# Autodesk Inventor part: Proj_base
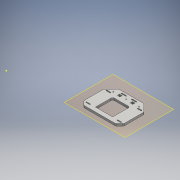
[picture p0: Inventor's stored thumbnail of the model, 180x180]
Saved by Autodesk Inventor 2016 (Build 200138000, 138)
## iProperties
Created: 2015-11
Part Number: Proj_base
Material: Generic
Document SubType Name: Modeling
Designer: John
Density: 1 g/cm^3
Appearance: Default
Author: John
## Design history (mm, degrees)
workplane "Work Plane1"
sketch "Sketch1"
  geometry: L1 (78.45, 44.2)-(78.45, -44.2) reference; L2 (63.45, -59.2)-(-63.45, -59.2) reference; L3 (-78.45, -44.2)-(-78.45, 44.2) reference; L4 (-63.45, 59.2)-(63.45, 59.2) reference; L5 (-161.15, -69.113)-(-161.15, -114.2) reference; L6 (-146.15, -129.2)-(-94.113, -129.2) reference; L7 (-83.507, -124.807)-(-66.893, -108.193) reference; L8 (-56.287, -103.8)-(56.287, -103.8) reference; L9 (66.893, -108.193)-(83.507, -124.807) reference; L10 (94.113, -129.2)-(146.15, -129.2) reference; L11 (161.15, -114.2)-(161.15, -69.113) reference; L12 (156.757, -58.507)-(140.143, -41.893) reference; L13 (135.75, -31.287)-(135.75, 31.287) reference; L14 (140.143, 41.893)-(156.757, 58.507) reference; L15 (161.15, 69.113)-(161.15, 114.2) reference; L16 (146.15, 129.2)-(94.113, 129.2) reference; L17 (83.507, 124.807)-(66.893, 108.193) reference; L18 (56.287, 103.8)-(-56.287, 103.8) reference; L19 (-66.893, 108.193)-(-83.507, 124.807) reference; L20 (-94.113, 129.2)-(-146.15, 129.2) reference; L21 (-161.15, 114.2)-(-161.15, 69.113) reference; L22 (-156.757, 58.507)-(-140.143, 41.893) reference; L23 (-135.75, 31.287)-(-135.75, -31.287) reference; L24 (-140.143, -41.893)-(-156.757, -58.507) reference; L25 (-93.775, 49.2)-(-93.775, 69.2) reference; L26 (-88.525, 69.2)-(-88.525, 49.2) reference; L27 (88.525, -69.2)-(88.525, -49.2) reference; L28 (93.775, -49.2)-(93.775, -69.2) reference; L29 (88.525, 49.2)-(88.525, 69.2) reference; L30 (93.775, 69.2)-(93.775, 49.2) reference; L31 (-93.775, -69.2)-(-93.775, -49.2) reference; L32 (-88.525, -49.2)-(-88.525, -69.2) reference; L33 (-116.55, 81.9)-(116.55, 81.9); L34 (116.55, 81.9)-(116.55, -81.9); L35 (116.55, -81.9)-(-116.55, -81.9); L36 (-116.55, -81.9)-(-116.55, 81.9); C1 r 19.5 at (-128.95, -97) reference; C2 r 19.5 at (-128.95, 97) reference; C3 r 19.5 at (128.95, 97) reference; C4 r 19.5 at (128.95, -97) reference; A1 r 15 centre (63.45, -44.2) between (63.45, -59.2) and (78.45, -44.2) reference; A2 r 15 centre (-63.45, -44.2) between (-78.45, -44.2) and (-63.45, -59.2) reference; A3 r 15 centre (-63.45, 44.2) between (-63.45, 59.2) and (-78.45, 44.2) reference; A4 r 15 centre (63.45, 44.2) between (78.45, 44.2) and (63.45, 59.2) reference; A5 r 15 centre (-146.15, -69.113) between (-156.757, -58.507) and (-161.15, -69.113) reference; A6 r 15 centre (-146.15, -114.2) between (-161.15, -114.2) and (-146.15, -129.2) reference; A7 r 15 centre (-94.113, -114.2) between (-94.113, -129.2) and (-83.507, -124.807) reference; A8 r 15 centre (-56.287, -118.8) between (-56.287, -103.8) and (-66.893, -108.193) reference; A9 r 15 centre (56.287, -118.8) between (66.893, -108.193) and (56.287, -103.8) reference; A10 r 15 centre (94.113, -114.2) between (83.507, -124.807) and (94.113, -129.2) reference; A11 r 15 centre (146.15, -114.2) between (146.15, -129.2) and (161.15, -114.2) reference; A12 r 15 centre (146.15, -69.113) between (161.15, -69.113) and (156.757, -58.507) reference; A13 r 15 centre (150.75, -31.287) between (135.75, -31.287) and (140.143, -41.893) reference; A14 r 15 centre (150.75, 31.287) between (140.143, 41.893) and (135.75, 31.287) reference; A15 r 15 centre (146.15, 69.113) between (156.757, 58.507) and (161.15, 69.113) reference; A16 r 15 centre (146.15, 114.2) between (161.15, 114.2) and (146.15, 129.2) reference; A17 r 15 centre (94.113, 114.2) between (94.113, 129.2) and (83.507, 124.807) reference; A18 r 15 centre (56.287, 118.8) between (56.287, 103.8) and (66.893, 108.193) reference; A19 r 15 centre (-56.287, 118.8) between (-66.893, 108.193) and (-56.287, 103.8) reference; A20 r 15 centre (-94.113, 114.2) between (-83.507, 124.807) and (-94.113, 129.2) reference; A21 r 15 centre (-146.15, 114.2) between (-146.15, 129.2) and (-161.15, 114.2) reference; A22 r 15 centre (-146.15, 69.113) between (-161.15, 69.113) and (-156.757, 58.507) reference; A23 r 15 centre (-150.75, 31.287) between (-135.75, 31.287) and (-140.143, 41.893) reference; A24 r 15 centre (-150.75, -31.287) between (-140.143, -41.893) and (-135.75, -31.287) reference; A25 r 2.625 centre (-91.15, 49.2) between (-93.775, 49.2) and (-88.525, 49.2) reference; A26 r 2.625 centre (-91.15, 69.2) between (-88.525, 69.2) and (-93.775, 69.2) reference; A27 r 2.625 centre (91.15, -69.2) between (88.525, -69.2) and (93.775, -69.2) reference; A28 r 2.625 centre (91.15, -49.2) between (93.775, -49.2) and (88.525, -49.2) reference; A29 r 2.625 centre (91.15, 49.2) between (88.525, 49.2) and (93.775, 49.2) reference; A30 r 2.625 centre (91.15, 69.2) between (93.775, 69.2) and (88.525, 69.2) reference; A31 r 2.625 centre (-91.15, -69.2) between (-93.775, -69.2) and (-88.525, -69.2) reference; A32 r 2.625 centre (-91.15, -49.2) between (-88.525, -49.2) and (-93.775, -49.2) reference; 1 further point
  constraints: 8 end point, 2 parallel, 1 horizontal, 1 perpendicular
  dimensions: "d0" = 12.7 distance from line of A26.centre L33; "d1" = 25.4 distance from line of A26.centre L36; "d2" = 25.4 distance from line of A30.centre L34 (= d1); "d3" = 12.7 distance from line of A27.centre L35 (= d0)
extrude "Extrusion1" new body sketch "Sketch1" distance "d4" = 12.7; taper "d5" = 0 deg
sketch "Sketch2"
  geometry: L1 (93.775, 69.2)-(93.775, 49.2) reference; L2 (88.525, 49.2)-(88.525, 69.2) reference; L3 (93.775, -49.2)-(93.775, -69.2) reference; L4 (88.525, -69.2)-(88.525, -49.2) reference; L5 (-88.525, -49.2)-(-88.525, -69.2) reference; L6 (-93.775, -69.2)-(-93.775, -49.2) reference; L7 (-88.525, 69.2)-(-88.525, 49.2) reference; L8 (-93.775, 49.2)-(-93.775, 69.2) reference; L9 (-101.15, 59.2)-(-81.15, 59.2); L10 (-101.15, 61.825)-(-81.15, 61.825); L11 (-81.15, 56.575)-(-101.15, 56.575); L12 (-101.15, -59.2)-(-81.15, -59.2); L13 (-101.15, -56.575)-(-81.15, -56.575); L14 (-81.15, -61.825)-(-101.15, -61.825); L15 (81.15, -59.2)-(101.15, -59.2); L16 (81.15, -56.575)-(101.15, -56.575); L17 (101.15, -61.825)-(81.15, -61.825); L18 (81.15, 59.2)-(101.15, 59.2); L19 (81.15, 56.575)-(101.15, 56.575); L20 (101.15, 61.825)-(81.15, 61.825); A1 r 2.625 centre (91.15, 69.2) between (93.775, 69.2) and (88.525, 69.2) reference; A2 r 2.625 centre (91.15, 49.2) between (88.525, 49.2) and (93.775, 49.2) reference; A3 r 2.625 centre (91.15, -69.2) between (88.525, -69.2) and (93.775, -69.2) reference; A4 r 2.625 centre (91.15, -49.2) between (93.775, -49.2) and (88.525, -49.2) reference; A5 r 2.625 centre (-91.15, -69.2) between (-93.775, -69.2) and (-88.525, -69.2) reference; A6 r 2.625 centre (-91.15, -49.2) between (-88.525, -49.2) and (-93.775, -49.2) reference; A7 r 2.625 centre (-91.15, 49.2) between (-93.775, 49.2) and (-88.525, 49.2) reference; A8 r 2.625 centre (-91.15, 69.2) between (-88.525, 69.2) and (-93.775, 69.2) reference; A9 r 2.625 centre (-101.15, 59.2) between (-101.15, 61.825) and (-101.15, 56.575); A10 r 2.625 centre (-81.15, 59.2) between (-81.15, 56.575) and (-81.15, 61.825); A11 r 2.625 centre (-101.15, -59.2) between (-101.15, -56.575) and (-101.15, -61.825); A12 r 2.625 centre (-81.15, -59.2) between (-81.15, -61.825) and (-81.15, -56.575); A13 r 2.625 centre (81.15, -59.2) between (81.15, -56.575) and (81.15, -61.825); A14 r 2.625 centre (101.15, -59.2) between (101.15, -61.825) and (101.15, -56.575); A15 r 2.625 centre (81.15, 59.2) between (81.15, 61.825) and (81.15, 56.575); A16 r 2.625 centre (101.15, 59.2) between (101.15, 56.575) and (101.15, 61.825); 5 further points
  constraints: 32 end point, 16 point on circle, 16 tangent, 8 centre point, 5 parallel, 4 equal length, 4 midpoint, 4 vertical alignment, 3 equal radius, 2 horizontal, 2 horizontal alignment, 2 point on line
  dimensions: "d7" = 5.25 distance between parallel lines of L10 L11; "d8" = 10 distance of A6.centre point (-91.15, -59.2); "d9" = 10 distance of A8.centre point (-91.15, 59.2) (= d8)
extrude "Extrusion2" cut sketch "Sketch2" stored distance "d10" = 12.7; taper "d11" = 0 deg
sketch "Sketch3"
  geometry: 1 further point
sketch "Sketch4"
  geometry: L1 (-101.15, 61.825)-(-81.15, 61.825) reference; L2 (-81.15, 56.575)-(-101.15, 56.575) reference; L3 (81.15, -56.575)-(101.15, -56.575) reference; L4 (101.15, -61.825)-(81.15, -61.825) reference; L5 (101.15, 56.575)-(81.15, 56.575) reference; L6 (81.15, 61.825)-(101.15, 61.825) reference; L7 (-101.15, -56.575)-(-81.15, -56.575) reference; L8 (-81.15, -61.825)-(-101.15, -61.825) reference; L9 (116.55, 81.9)-(-116.55, 81.9) reference; L10 (-116.55, 81.9)-(-116.55, -81.9) reference; L11 (-116.55, -81.9)-(116.55, -81.9) reference; L12 (116.55, -81.9)-(116.55, 81.9) reference; L13 (-45, 48.4)-(-30, 48.4); L14 (-30, 48.4)-(-30, 35.4); L15 (-30, 35.4)-(-45, 35.4); L16 (-45, 35.4)-(-45, 48.4); L17 (30, 48.4)-(45, 48.4); L18 (45, 48.4)-(45, 35.4); L19 (45, 35.4)-(30, 35.4); L20 (30, 35.4)-(30, 48.4); C1 r 2.625 at (0, 41.9); C2 r 2.625 at (75, 41.9); C3 r 2.625 at (-75, 41.9); A1 r 2.625 centre (-101.15, 59.2) between (-101.15, 61.825) and (-101.15, 56.575) reference; A2 r 2.625 centre (-81.15, 59.2) between (-81.15, 56.575) and (-81.15, 61.825) reference; A3 r 2.625 centre (81.15, -59.2) between (81.15, -56.575) and (81.15, -61.825) reference; A4 r 2.625 centre (101.15, -59.2) between (101.15, -61.825) and (101.15, -56.575) reference; A5 r 2.625 centre (101.15, 59.2) between (101.15, 56.575) and (101.15, 61.825) reference; A6 r 2.625 centre (81.15, 59.2) between (81.15, 61.825) and (81.15, 56.575) reference; A7 r 2.625 centre (-101.15, -59.2) between (-101.15, -56.575) and (-101.15, -61.825) reference; A8 r 2.625 centre (-81.15, -59.2) between (-81.15, -61.825) and (-81.15, -56.575) reference; 6 further points
  constraints: 16 end point, 5 midpoint, 4 horizontal alignment, 4 parallel, 3 centre point, 2 equal radius, 2 horizontal, 2 perpendicular, 2 point on line, 1 collinear, 1 vertical alignment
  dimensions: "d12" = 30 distance from line of C1.centre L14; "d13" = 5.25 diameter of C1; "d14" = 30 distance from line of L16 C3.centre (= d12); "d15" = 30 distance of point (45, 41.9) C2.centre (= d12); "d16" = 30 distance from line of C1.centre L20 (= d12); "d17" = 13 distance between parallel lines of L15 L13; "d18" = 15 distance of L14.end L15.end; "d19" = 40 distance from line of L9 C1.centre
extrude "Extrusion3" cut sketch "Sketch4" stored distance "d20" = 12.7; taper "d21" = 0 deg
sketch "Sketch5"
  geometry: L1 (-45, 35.4)-(-45, 48.4) reference; L2 (-45, 48.4)-(-30, 48.4) reference; L3 (-30, 48.4)-(-30, 35.4) reference; L4 (-30, 35.4)-(-45, 35.4) reference; L5 (30, 35.4)-(30, 48.4) reference; L6 (30, 48.4)-(45, 48.4) reference; L7 (45, 48.4)-(45, 35.4) reference; L8 (45, 35.4)-(30, 35.4) reference; L9 (-101.15, 61.825)-(-81.15, 61.825) reference; L10 (-81.15, 56.575)-(-101.15, 56.575) reference; L11 (81.15, -56.575)-(101.15, -56.575) reference; L12 (101.15, -61.825)-(81.15, -61.825) reference; L13 (101.15, 56.575)-(81.15, 56.575) reference; L14 (81.15, 61.825)-(101.15, 61.825) reference; L15 (-101.15, -56.575)-(-81.15, -56.575) reference; L16 (-81.15, -61.825)-(-101.15, -61.825) reference; L17 (116.55, 81.9)-(-116.55, 81.9) reference; L18 (-116.55, 81.9)-(-116.55, -81.9) reference; L19 (-116.55, -81.9)-(116.55, -81.9) reference; L20 (116.55, -81.9)-(116.55, 81.9) reference; L21 (-50, -81.9)-(50, -81.9); L22 (50, -81.9)-(50, -6.9); L23 (50, -6.9)-(-50, -6.9); L24 (-50, -6.9)-(-50, -81.9); C1 r 2.625 at (75, 41.9) reference; C2 r 2.625 at (0, 41.9) reference; C3 r 2.625 at (-75, 41.9) reference; A1 r 2.625 centre (-101.15, 59.2) between (-101.15, 61.825) and (-101.15, 56.575) reference; A2 r 2.625 centre (-81.15, 59.2) between (-81.15, 56.575) and (-81.15, 61.825) reference; A3 r 2.625 centre (81.15, -59.2) between (81.15, -56.575) and (81.15, -61.825) reference; A4 r 2.625 centre (101.15, -59.2) between (101.15, -61.825) and (101.15, -56.575) reference; A5 r 2.625 centre (101.15, 59.2) between (101.15, 56.575) and (101.15, 61.825) reference; A6 r 2.625 centre (81.15, 59.2) between (81.15, 61.825) and (81.15, 56.575) reference; A7 r 2.625 centre (-101.15, -59.2) between (-101.15, -56.575) and (-101.15, -61.825) reference; A8 r 2.625 centre (-81.15, -59.2) between (-81.15, -61.825) and (-81.15, -56.575) reference; 2 further points
  constraints: 8 end point, 2 midpoint, 2 parallel, 1 horizontal, 1 perpendicular, 1 point on line
  dimensions: "d22" = 100 distance of L22.end L23.end; "d23" = 75 distance of L21.end L22.end
extrude "Extrusion4" cut sketch "Sketch5" distance "d24" = 12.7; taper "d25" = 0 deg
fillet "Fillet2" dims "d26" = 10
chamfer "Chamfer1" distance "d27" = 30; stored, may be unused: second distance "d28" = 2, angle "d29" = 45 deg
fillet "Fillet3" dims "d30" = 10
node "Direct Edit1"
sketch "Sketch6"
  geometry: L1 (-113.621, 24.829)-(-74.479, 63.971) reference; L2 (-116.55, 17.758)-(-116.55, -77.758) reference; L3 (-89.479, -108.971)-(-113.621, -84.829) reference; L4 (-82.408, -111.9)-(-60, -111.9) reference; L5 (-50, -101.9)-(-50, -16.9) reference; L6 (-40, -6.9)-(40, -6.9) reference; L7 (50, -16.9)-(50, -101.9) reference; L8 (60, -111.9)-(82.408, -111.9) reference; L9 (113.621, -84.829)-(89.479, -108.971) reference; L10 (116.55, -77.758)-(116.55, 17.758) reference; L11 (74.479, 63.971)-(113.621, 24.829) reference; L12 (67.408, 66.9)-(-67.408, 66.9) reference; L13 (-45, 35.4)-(-45, 48.4) reference; L14 (-45, 48.4)-(-30, 48.4) reference; L15 (-30, 48.4)-(-30, 35.4) reference; L16 (-30, 35.4)-(-45, 35.4) reference; L17 (30, 35.4)-(30, 48.4) reference; L18 (30, 48.4)-(45, 48.4) reference; L19 (45, 48.4)-(45, 35.4) reference; L20 (45, 35.4)-(30, 35.4) reference; L21 (-101.15, 31.825)-(-81.15, 31.825) reference; L22 (-81.15, 26.575)-(-101.15, 26.575) reference; L23 (81.15, -86.575)-(101.15, -86.575) reference; L24 (101.15, -91.825)-(81.15, -91.825) reference; L25 (101.15, 26.575)-(81.15, 26.575) reference; L26 (81.15, 31.825)-(101.15, 31.825) reference; L27 (-101.15, -86.575)-(-81.15, -86.575) reference; L28 (-81.15, -91.825)-(-101.15, -91.825) reference; L29 (-42.5, 58.4)-(-17.5, 58.4); L30 (-42.5, 61.025)-(-17.5, 61.025); L31 (-17.5, 55.775)-(-42.5, 55.775); L32 (17.5, 58.4)-(42.5, 58.4); L33 (17.5, 61.025)-(42.5, 61.025); L34 (42.5, 55.775)-(17.5, 55.775); L35 (-30, 48.4)-(-45, 48.4) reference; C1 r 2.625 at (75, 41.9) reference; C2 r 2.625 at (0, 41.9) reference; C3 r 2.625 at (-75, 41.9) reference; C4 r 2.625 at (0, 41.9) reference; A1 r 10 centre (-67.408, 56.9) between (-67.408, 66.9) and (-74.479, 63.971) reference; A2 r 10 centre (-106.55, 17.758) between (-113.621, 24.829) and (-116.55, 17.758) reference; A3 r 10 centre (-106.55, -77.758) between (-116.55, -77.758) and (-113.621, -84.829) reference; A4 r 10 centre (-82.408, -101.9) between (-89.479, -108.971) and (-82.408, -111.9) reference; A5 r 10 centre (-60, -101.9) between (-60, -111.9) and (-50, -101.9) reference; A6 r 10 centre (-40, -16.9) between (-40, -6.9) and (-50, -16.9) reference; A7 r 10 centre (40, -16.9) between (50, -16.9) and (40, -6.9) reference; A8 r 10 centre (60, -101.9) between (50, -101.9) and (60, -111.9) reference; A9 r 10 centre (82.408, -101.9) between (82.408, -111.9) and (89.479, -108.971) reference; A10 r 10 centre (106.55, -77.758) between (113.621, -84.829) and (116.55, -77.758) reference; A11 r 10 centre (106.55, 17.758) between (116.55, 17.758) and (113.621, 24.829) reference; A12 r 10 centre (67.408, 56.9) between (74.479, 63.971) and (67.408, 66.9) reference; A13 r 2.625 centre (-101.15, 29.2) between (-101.15, 31.825) and (-101.15, 26.575) reference; A14 r 2.625 centre (-81.15, 29.2) between (-81.15, 26.575) and (-81.15, 31.825) reference; A15 r 2.625 centre (81.15, -89.2) between (81.15, -86.575) and (81.15, -91.825) reference; A16 r 2.625 centre (101.15, -89.2) between (101.15, -91.825) and (101.15, -86.575) reference; A17 r 2.625 centre (101.15, 29.2) between (101.15, 26.575) and (101.15, 31.825) reference; A18 r 2.625 centre (81.15, 29.2) between (81.15, 31.825) and (81.15, 26.575) reference; A19 r 2.625 centre (-101.15, -89.2) between (-101.15, -86.575) and (-101.15, -91.825) reference; A20 r 2.625 centre (-81.15, -89.2) between (-81.15, -91.825) and (-81.15, -86.575) reference; A21 r 2.625 centre (-42.5, 58.4) between (-42.5, 61.025) and (-42.5, 55.775); A22 r 2.625 centre (-17.5, 58.4) between (-17.5, 55.775) and (-17.5, 61.025); A23 r 2.625 centre (17.5, 58.4) between (17.5, 61.025) and (17.5, 55.775); A24 r 2.625 centre (42.5, 58.4) between (42.5, 55.775) and (42.5, 61.025); 3 further points
  constraints: 16 end point, 8 point on circle, 8 tangent, 4 centre point, 2 equal radius, 2 midpoint, 2 parallel, 2 point on line, 1 collinear, 1 horizontal
  dimensions: "d37" = 10 distance between parallel lines of L35 L29; "d38" = 30 horizontal distance of C2.centre point (30, 58.4); "d39" = 30 horizontal distance of C2.centre point (-30, 58.4) (= d38); "d40" = 25 distance of L29.start L29.end
extrude "Extrusion5" cut sketch "Sketch6" stored distance "d41" = 10; taper "d42" = 0 deg
node "Direct Edit2"
node "Direct Edit3"
node "Direct Edit4"
sketch "Sketch7"
  geometry: L1 (-50, -101.9)-(-50, 3.1) reference; L2 (-40, 13.1)-(40, 13.1) reference; L3 (50, 3.1)-(50, -101.9) reference; L4 (60, -111.9)-(88.408, -111.9) reference; L5 (113.621, -90.829)-(95.479, -108.971) reference; L6 (116.55, -83.758)-(116.55, 23.758) reference; L7 (75.479, 68.971)-(113.621, 30.829) reference; L8 (68.408, 71.9)-(-68.408, 71.9) reference; L9 (-113.621, 30.829)-(-75.479, 68.971) reference; L10 (-116.55, 23.758)-(-116.55, -83.758) reference; L11 (-95.479, -108.971)-(-113.621, -90.829) reference; L12 (-88.408, -111.9)-(-60, -111.9) reference; L13 (-42.5, 61.025)-(-17.5, 61.025) reference; L14 (-17.5, 55.775)-(-42.5, 55.775) reference; L15 (17.5, 61.025)-(42.5, 61.025) reference; L16 (42.5, 55.775)-(17.5, 55.775) reference; L17 (-45, 35.4)-(-45, 48.4) reference; L18 (-45, 48.4)-(-30, 48.4) reference; L19 (-30, 48.4)-(-30, 35.4) reference; L20 (-30, 35.4)-(-45, 35.4) reference; L21 (30, 35.4)-(30, 48.4) reference; L22 (30, 48.4)-(45, 48.4) reference; L23 (45, 48.4)-(45, 35.4) reference; L24 (45, 35.4)-(30, 35.4) reference; L25 (-101.15, 31.825)-(-81.15, 31.825) reference; L26 (-81.15, 26.575)-(-101.15, 26.575) reference; L27 (81.15, -86.575)-(101.15, -86.575) reference; L28 (101.15, -91.825)-(81.15, -91.825) reference; L29 (101.15, 26.575)-(81.15, 26.575) reference; L30 (81.15, 31.825)-(101.15, 31.825) reference; L31 (-101.15, -86.575)-(-81.15, -86.575) reference; L32 (-81.15, -91.825)-(-101.15, -91.825) reference; L33 (60, -111.9)-(-60, -111.9); L34 (-50, -86.9)-(50, -86.9); C1 r 2.625 at (75, 41.9) reference; C2 r 2.625 at (0, 41.9) reference; C3 r 2.625 at (-75, 41.9) reference; A1 r 10 centre (-40, 3.1) between (-40, 13.1) and (-50, 3.1) reference; A2 r 10 centre (40, 3.1) between (50, 3.1) and (40, 13.1) reference; A3 r 10 centre (60, -101.9) between (50, -101.9) and (60, -111.9) reference; A4 r 10 centre (88.408, -101.9) between (88.408, -111.9) and (95.479, -108.971) reference; A5 r 10 centre (106.55, -83.758) between (113.621, -90.829) and (116.55, -83.758) reference; A6 r 10 centre (106.55, 23.758) between (116.55, 23.758) and (113.621, 30.829) reference; A7 r 10 centre (68.408, 61.9) between (75.479, 68.971) and (68.408, 71.9) reference; A8 r 10 centre (-68.408, 61.9) between (-68.408, 71.9) and (-75.479, 68.971) reference; A9 r 10 centre (-106.55, 23.758) between (-113.621, 30.829) and (-116.55, 23.758) reference; A10 r 10 centre (-106.55, -83.758) between (-116.55, -83.758) and (-113.621, -90.829) reference; A11 r 10 centre (-88.408, -101.9) between (-95.479, -108.971) and (-88.408, -111.9) reference; A12 r 10 centre (-60, -101.9) between (-60, -111.9) and (-50, -101.9) reference; A13 r 2.625 centre (-42.5, 58.4) between (-42.5, 61.025) and (-42.5, 55.775) reference; A14 r 2.625 centre (-17.5, 58.4) between (-17.5, 55.775) and (-17.5, 61.025) reference; A15 r 2.625 centre (17.5, 58.4) between (17.5, 61.025) and (17.5, 55.775) reference; A16 r 2.625 centre (42.5, 58.4) between (42.5, 55.775) and (42.5, 61.025) reference; A17 r 2.625 centre (-101.15, 29.2) between (-101.15, 31.825) and (-101.15, 26.575) reference; A18 r 2.625 centre (-81.15, 29.2) between (-81.15, 26.575) and (-81.15, 31.825) reference; A19 r 2.625 centre (81.15, -89.2) between (81.15, -86.575) and (81.15, -91.825) reference; A20 r 2.625 centre (101.15, -89.2) between (101.15, -91.825) and (101.15, -86.575) reference; A21 r 2.625 centre (101.15, 29.2) between (101.15, 26.575) and (101.15, 31.825) reference; A22 r 2.625 centre (81.15, 29.2) between (81.15, 31.825) and (81.15, 26.575) reference; A23 r 2.625 centre (-101.15, -89.2) between (-101.15, -86.575) and (-101.15, -91.825) reference; A24 r 2.625 centre (-81.15, -89.2) between (-81.15, -91.825) and (-81.15, -86.575) reference; 1 further point
  constraints: 4 end point, 2 point on line, 1 horizontal, 1 perpendicular, 1 tangent
  dimensions: "d61" = 25 distance between parallel lines of L33 L34
extrude "Extrusion6" join sketch "Sketch7" stored distance "d62" = 10; taper "d63" = 0 deg
body "Solid1"
node "Reference1"
node "Projected Loop1"
node "Projected Loop2"
node "Projected Loop3"
node "Projected Loop4"
move_body "Move1" dims "d32" = -30
move_body "Move2" dims "d35" = 15
move_body "Move3" dims "d44" = 5
move_body "Move4" dims "d46" = 6
move_body "Move5" dims "d49" = -6
move_body "Move6" dims "d52" = -6
move_body "Move7" dims "d55" = 6
move_body "Move8" dims "d59" = 20
other parameters: "d31" = 0, "d33" = 0, "d34" = 0, "d36" = 0, "d43" = 0, "d45" = 0, "d47" = 0, "d48" = 0, "d50" = 0, "d51" = 0, "d53" = 0, "d54" = 0, "d56" = 0, "d57" = 0, "d58" = 0, "d60" = 0
